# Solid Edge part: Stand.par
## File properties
Title: Stand
Author: windows
Template: Iso Metric Part.par
Last saved by: windows
Revision: 4
Application: Solid Edge
Username: windows
Density: 886,000 kg/m^3
Accuracy: 0,990
Material: Polyethylene, low density
Face Style: Blue
Fill Style: ANSI34(Plastic)
Virtual Style: ANSI34(Plastic)
Grouping: Non-metals\Plastics
LibraryName: Materials
Coef. of Thermal Exp: 0.00016
Thermal Conductivity: 3.9
Specific Heat: 2219.0
Modulus of Elasticity: 144789897.0
Poisson's Ratio: 0.35
Yield Stress: 9652659.8
Ultimate Stress: 0.0
Elongation: 0.0
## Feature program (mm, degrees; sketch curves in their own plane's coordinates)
sketch for "unnamed RevolvedProtrusion 1" plane through (0, 0, 0) normal (1, 0, 0) x-axis (0, 1, 0)
  line (8.18, 15) -> (6.0823, 15)
  line (6.0823, 15) -> (6.0823, 3)
  line (6.0823, 3) -> (0, 3)
  line (0, 3) -> (0, 0)
  line (0, 0) -> (8.18, 0)
  line (8.18, 0) -> (8.18, 15)
revolve "unnamed RevolvedProtrusion 1" add finite
logasc func "Lip_Groove_1"  LipOrGrooveWidth = 1 mm; LipOrGrooveHeight = 1 mm
logasc func "Lip_Groove_2"  LipOrGrooveWidth = 1 mm; LipOrGrooveHeight = 1 mm
logasc func "Lip_Groove_3"  LipOrGrooveWidth = 1 mm; LipOrGrooveHeight = 1 mm
logasc func "Lip_Groove_4"  LipOrGrooveWidth = 1 mm; LipOrGrooveHeight = 1 mm
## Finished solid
Body 1: solid body, 11 faces, 24 edges, 16 vertices.
  Faces by surface: plane 7, cylinder 4
  Edges by curve: line 16, circle 8
Bounding box of the edges (mm): 10.180 x 18.360 x 15.000, from (-9.18, -9.18, 0) to (1, 9.18, 15).
Cylindrical faces by radius (mm): R5.0823 x1, R6.0823 x1, R8.18 x1, R9.18 x1
Planar faces by outward normal: +x 3, +z 2, -z 2
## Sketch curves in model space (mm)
line (0, 8.18, 0) -> (0, 8.18, 15)
line (0, 8.18, 15) -> (0, 6.0823, 15)
line (0, 6.0823, 15) -> (0, 6.0823, 3)
line (0, 6.0823, 3) -> (0, 0, 3)
line (0, 0, 3) -> (0, 0, 0)
line (0, 0, 0) -> (0, 8.18, 0)
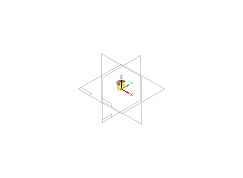
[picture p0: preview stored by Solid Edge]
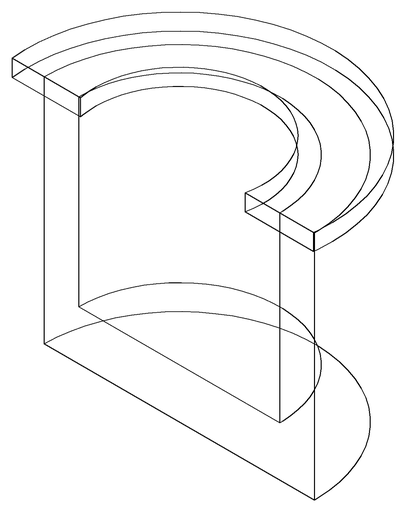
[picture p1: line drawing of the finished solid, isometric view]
